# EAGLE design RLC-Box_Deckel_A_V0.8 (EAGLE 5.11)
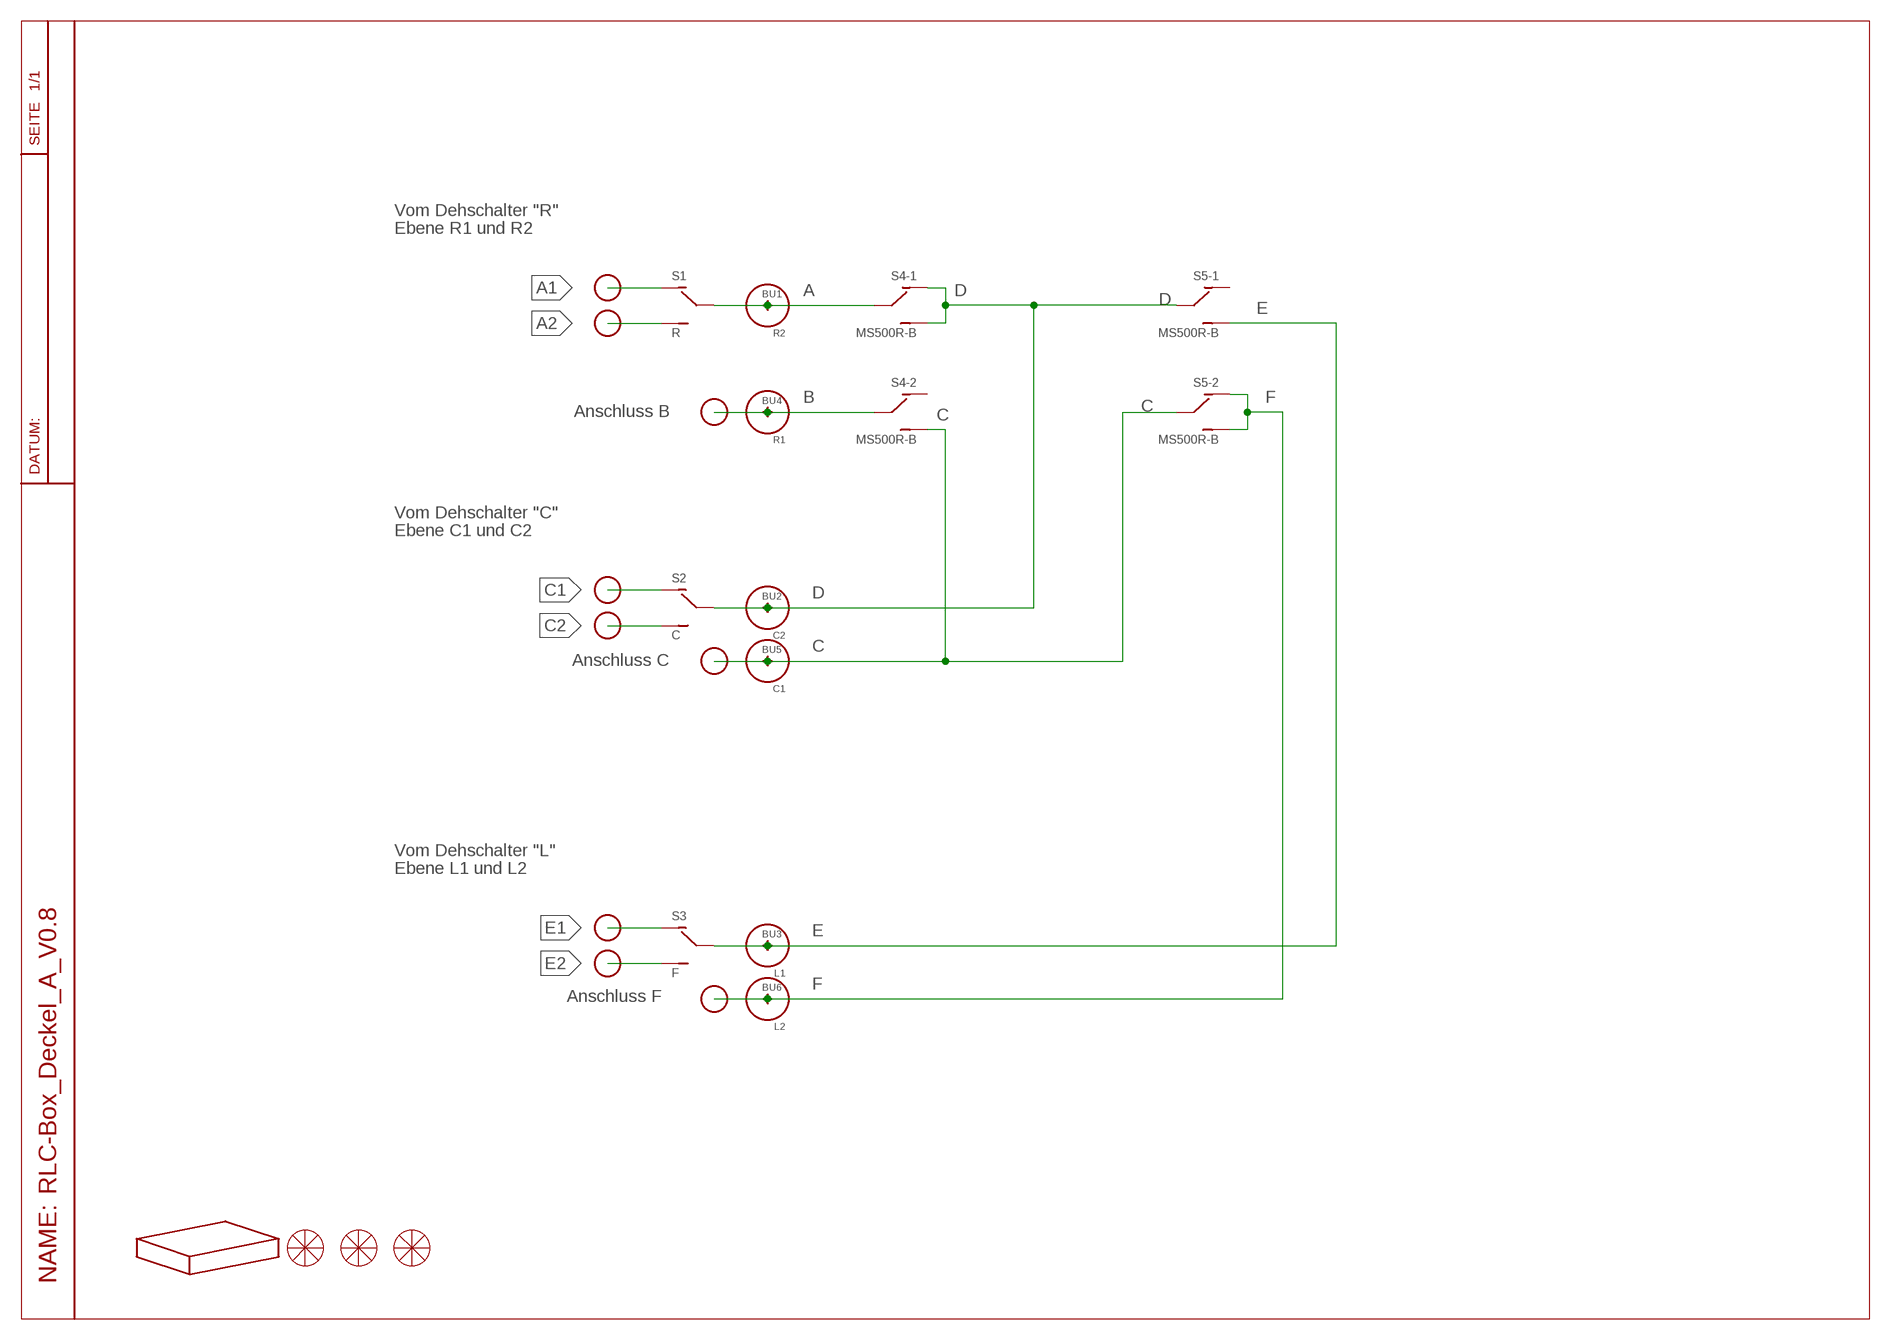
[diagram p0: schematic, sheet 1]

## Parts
BU1  R2  PK10AP  [PK10AP]
BU2  C2  PK10AP  [PK10AP]
BU3  L1  PK10AP  [PK10AP]
BU4  R1  PK10AP  [PK10AP]
BU5  C1  PK10AP  [PK10AP]
BU6  L2  PK10AP  [PK10AP]
P1  PAD-01  PAD-01SMD  [PAD-01-SMD]
P2  PAD-01  PAD-01SMD  [PAD-01-SMD]
P3  PAD-01  PAD-01SMD  [PAD-01-SMD]
P4  PAD-01  PAD-01SMD  [PAD-01-SMD]
P5  PAD-01  PAD-01SMD  [PAD-01-SMD]
P6  PAD-01  PAD-01SMD  [PAD-01-SMD]
P7  PAD-01  PAD-01SMD  [PAD-01-SMD]
P8  PAD-01  PAD-01SMD  [PAD-01-SMD]
P9  PAD-01  PAD-01SMD  [PAD-01-SMD]
S1  R  1XUMT1813  [T8013-1XUM]
S2  C  1XUMT1813  [T8013-1XUM]
S3  F  1XUMT1813  [T8013-1XUM]
S4  MS500R-B  MS500R-BT8011  [T8011-2XUM]
S5  MS500R-B  MS500R-BT8011  [T8011-2XUM]
U$1  DECKEL  [GEHÄUSE]
U$5  SKALA24  SKALA24K  [SKALE24]
U$6  SKALA24  SKALA24K  [SKALE24]
U$9  SKALA24  SKALA24G  [SKALE25-2]

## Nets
A: BU1.1 S1.2 S4.2
A1: P1.P$1 S1.1
A2: P2.P$1 S1.3
B: BU4.1 P3.P$1 S4.5
C: BU5.1 P6.P$1 S4.6 S5.5
C1: P4.P$1 S2.1
C2: P5.P$1 S2.3
D: BU2.1 S2.2 S4.1 S4.3 S5.2
E: BU3.1 S3.2 S5.3
E1: P7.P$1 S3.1
E2: P8.P$1 S3.3
F: BU6.1 P9.P$1 S5.4 S5.6
Unconnected: S4.4 S5.1

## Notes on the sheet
- Vom Dehschalter "R"
- Ebene R1 und R2
- Anschluss B
- Vom Dehschalter "C"
- Ebene C1 und C2
- Anschluss C
- Vom Dehschalter "L"
- Ebene L1 und L2
- Anschluss F

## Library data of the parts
BU1-BU6 = MB:PK10AP
P1-P9 = Connect:PAD-01
S1-S3 = Schalter:1XUM
S4 S5 = Schalter:MS500R-B
U$1 = RLC-BOX:DECKEL
U$5 U$6 U$9 = RLC-BOX:SKALA24

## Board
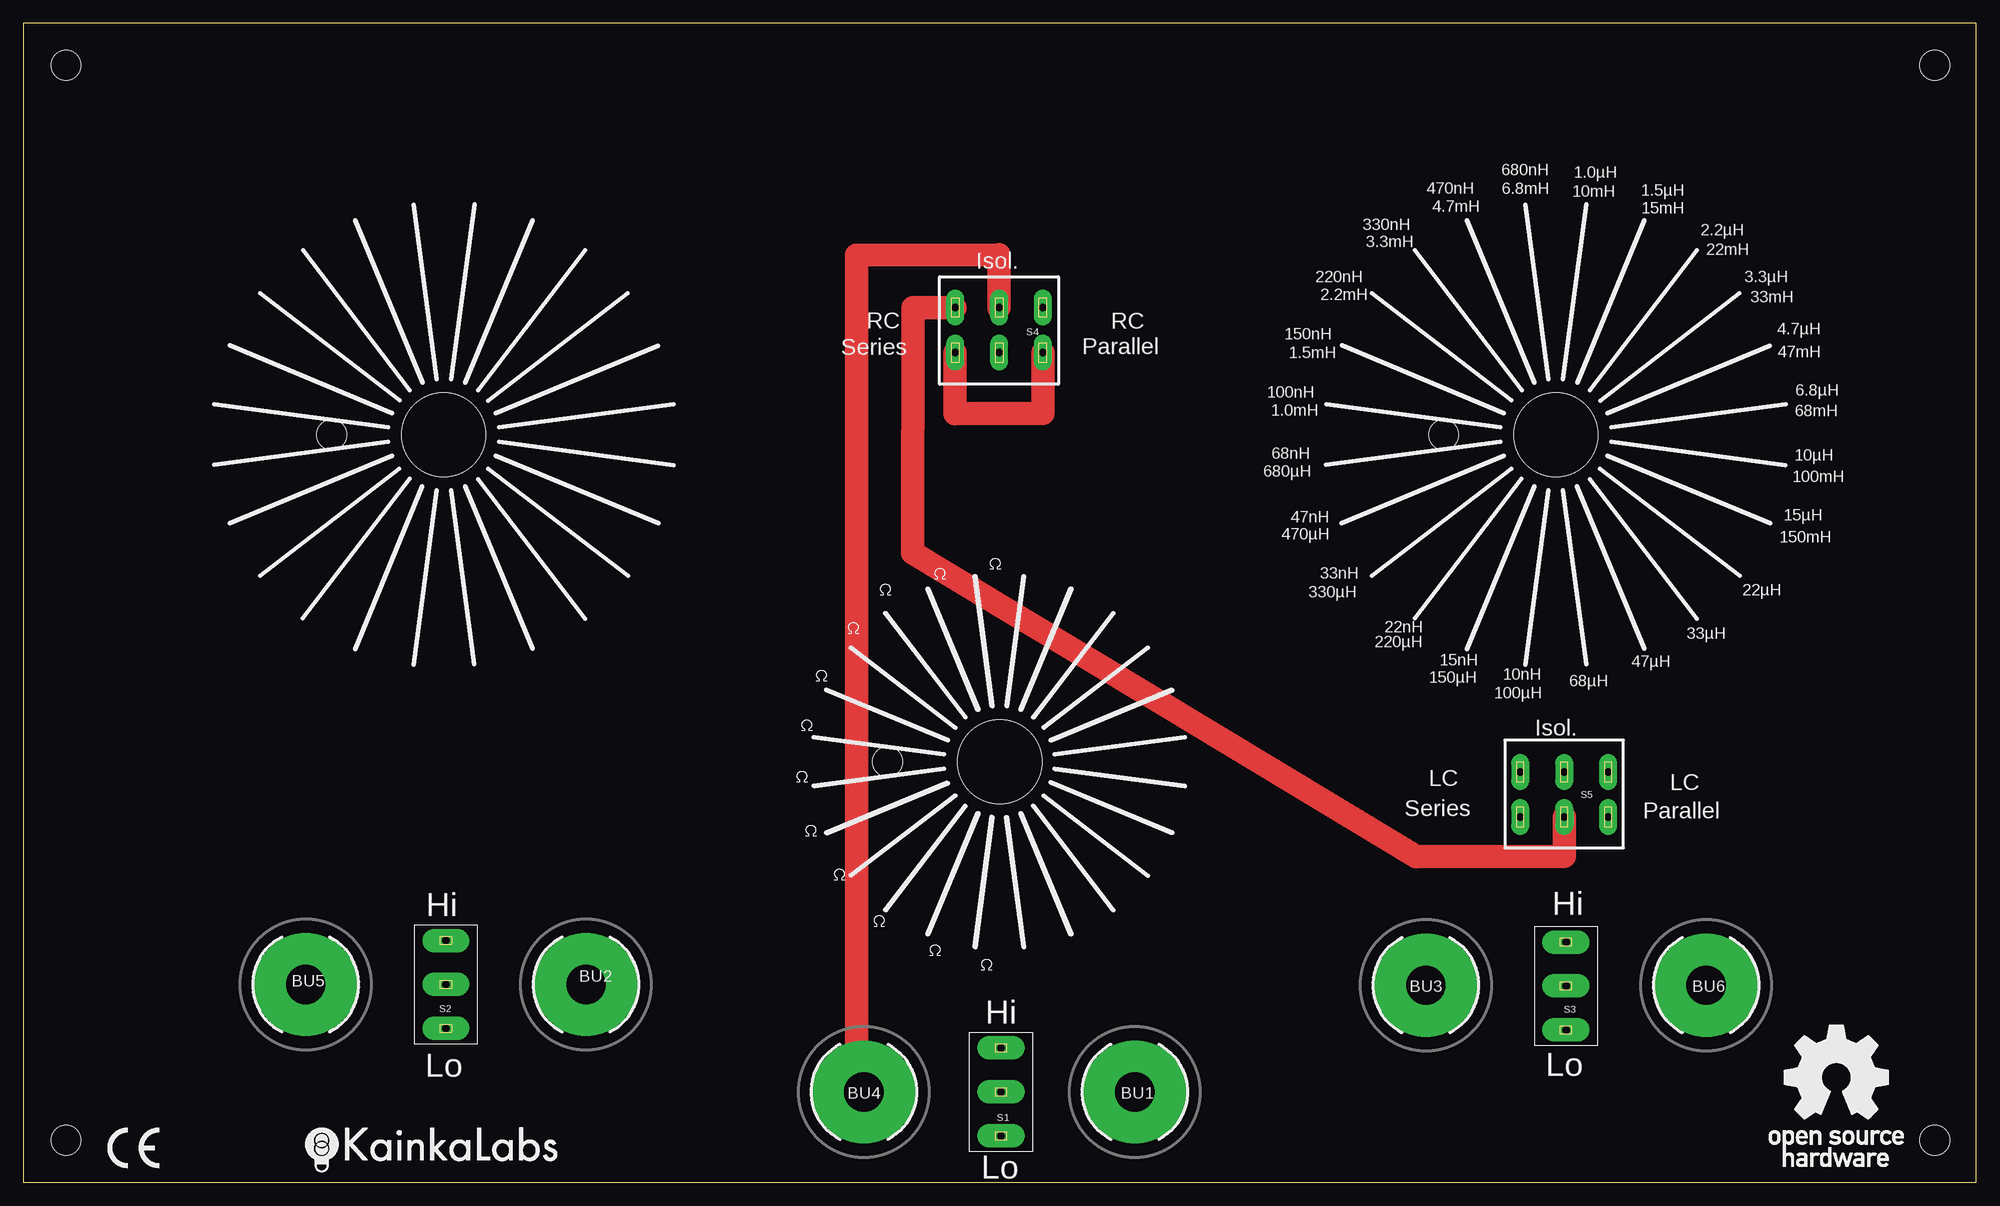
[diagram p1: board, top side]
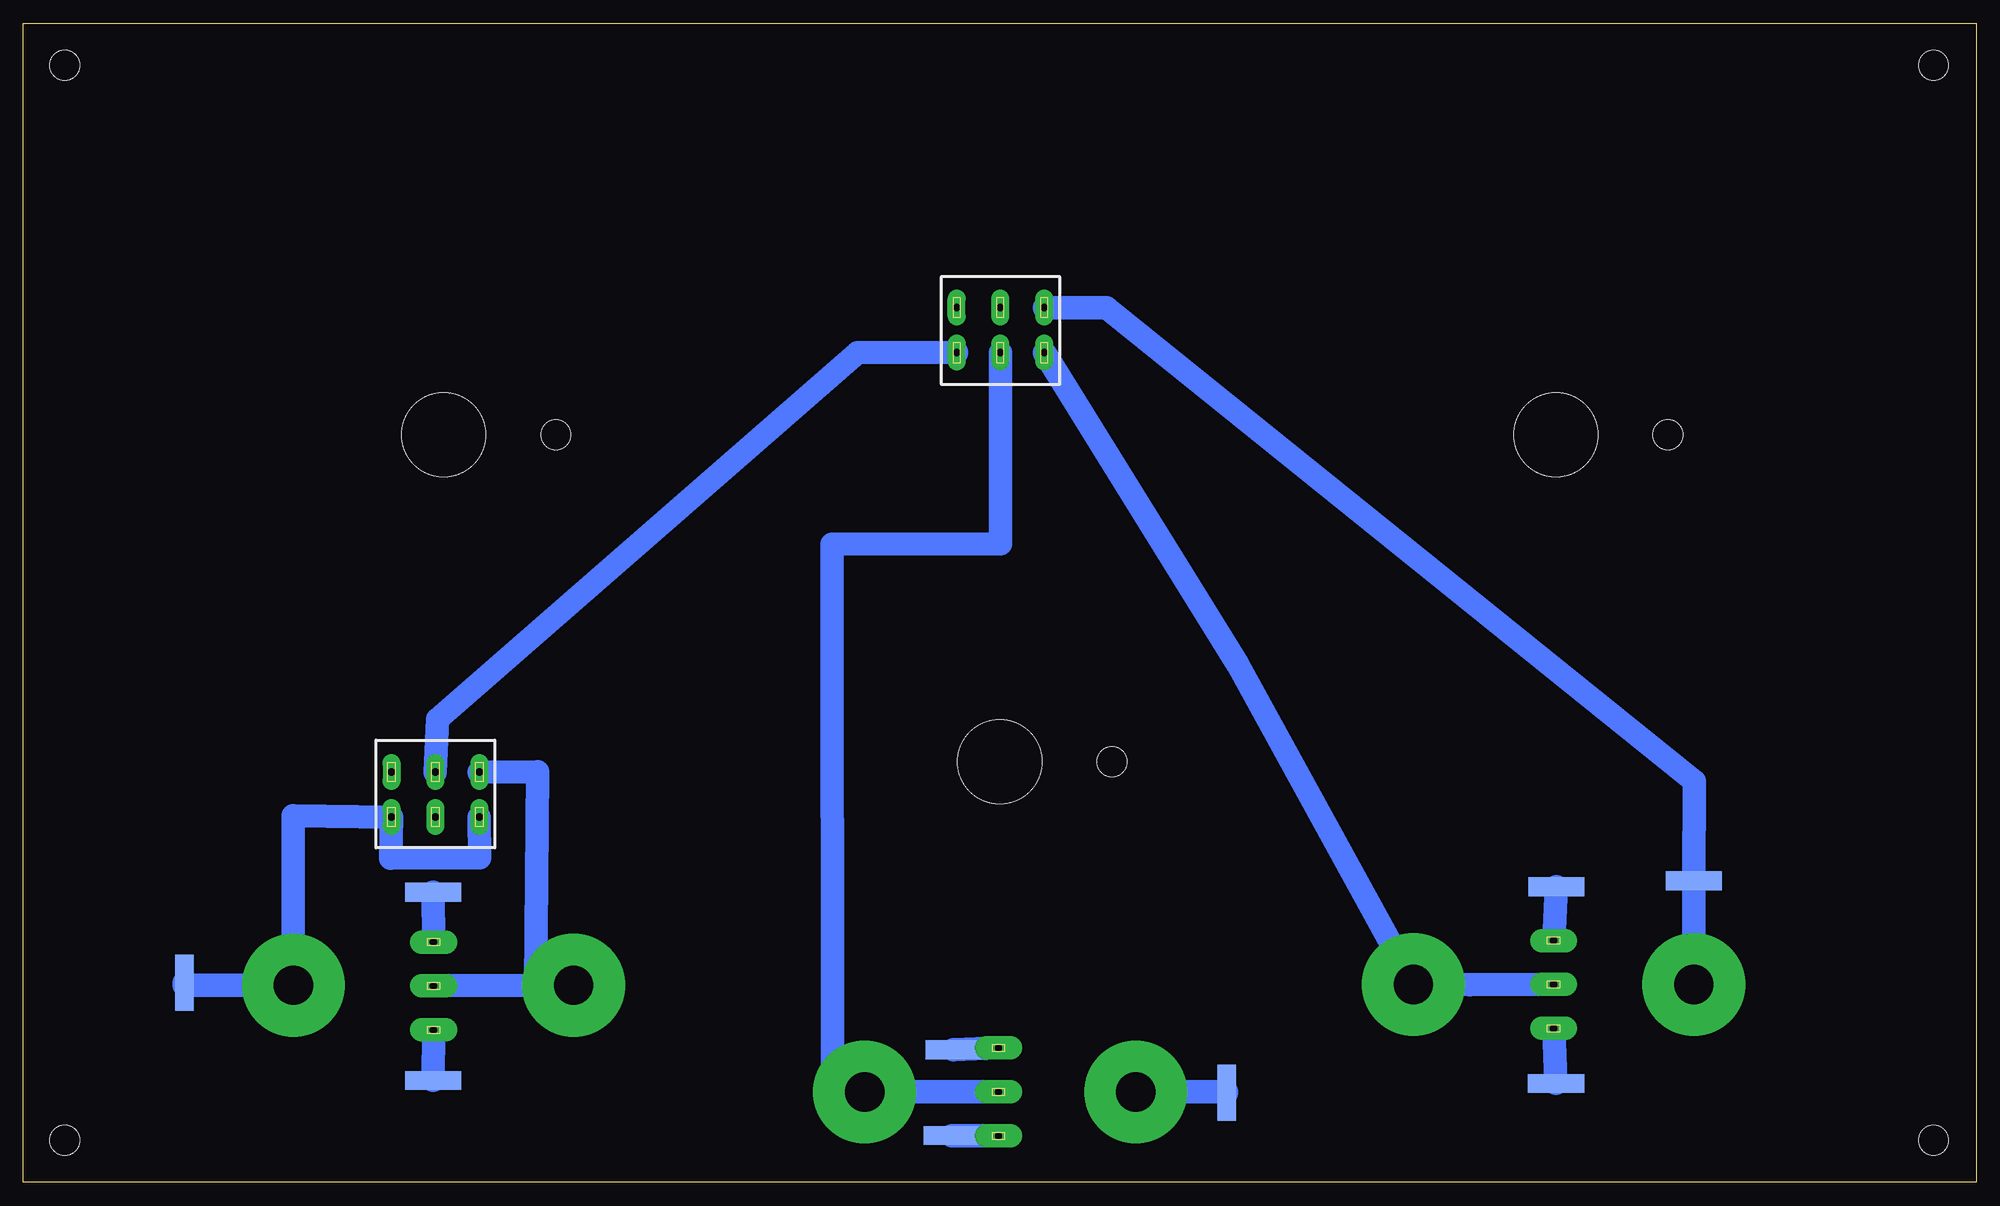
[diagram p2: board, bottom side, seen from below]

Size 209 x 124 mm. Coordinates in mm from the lower left corner, seen from the top.
Copper layers (1*16): Top 0.035mm / dielectric 1.5mm / Bottom 0.035mm
Design rules "default": minimum track width 10mil, minimum drill 23mil, track to track 8mil, track to pad 8mil, pad to pad 8mil, via to via 8mil, smd to smd 8mil, copper to edge 40mil, drill to drill 8mil, minimum pad ring 10mil, minimum via ring 8mil, stop-mask expansion 4mil, vias tented up to drill 0mil, thermal gap 20mil

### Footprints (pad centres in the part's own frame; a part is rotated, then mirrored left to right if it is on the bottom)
PK10AP = drill 4.2 pad 11 round: 1 0,0
PAD-01-SMD = smd 6 x 2: P$1 0,0
T8013-1XUM = drill 0.8 pad 2.54 long: 1 0,4.7; 2 0,0; 3 0,-4.7
T8011-2XUM = drill 0.8 pad 1.93 long: 1 -2.415,4.7; 2 -2.415,0; 3 -2.415,-4.7; 4 2.415,4.7; 5 2.415,0; 6 2.415,-4.7
GEHÄUSE = hole 3.2: 204.567,119.503; 204.567,4.503; 4.567,4.503; 4.567,119.503; 152,80; 92.5,45; 33,80 | hole 9: 164,80; 104.5,45; 45,80

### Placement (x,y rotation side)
BU1  118.96,9.67 0 top
BU2  60.22,21.16 0 top
BU3  150.11,21.09 0 top
BU4  89.96,9.67 0 top
BU5  30.22,21.16 0 top
BU6  180.11,21.09 0 top
P1  109.63,4.99 180 bottom
P2  109.46,14.19 0 bottom
P3  80.22,9.59 270 bottom
P4  44.96,10.57 0 bottom
P5  44.93,31.62 0 bottom
P6  30.23,32.26 180 bottom
P7  165.13,10.9 0 bottom
P8  165.13,31.04 0 bottom
P9  191.77,21.34 270 bottom
S1  104.63,9.67 180 top
S2  45.22,21.16 180 top
S3  165.1,21 180 top
S4  104.42,91.18 90 bottom
S5  164.9,41.48 270 top
U$1  0,0 0 top
U$2  [KAIKALABS27]  30.17,1.07 0 top
U$3  [CE6MM]  9.02,1.52 0 top
U$4  [OSH15MM]  186.82,1.65 0 top
U$5  104.41,45.02 0 top
U$6  104.5,45 0 top
U$7  SKALA24  [SKALE25-2]  164,80 0 top
U$9  45,80 0 top
U$11  [OHM1,5MM-S]  91.63,62.82 0 top
U$12  [OHM1,5MM-S]  97.46,64.5 0 top
U$13  [OHM1,5MM-S]  103.38,65.57 0 top
U$14  [OHM1,5MM-S]  88.2,58.7 0 top
U$15  [OHM1,5MM-S]  84.79,53.6 0 top
U$16  [OHM1,5MM-S]  83.21,48.28 0 top
U$17  [OHM1,5MM-S]  82.69,42.79 0 top
U$18  [OHM1,5MM-S]  83.65,37.03 0 top
U$19  [OHM1,5MM-S]  86.71,32.33 0 top
U$20  [OHM1,5MM-S]  90.96,27.36 0 top
U$21  [OHM1,5MM-S]  96.95,24.22 0 top
U$22  [OHM1,5MM-S]  102.45,22.69 0 top

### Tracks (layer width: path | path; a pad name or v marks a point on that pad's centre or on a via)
A
  Bottom 2.54: S1.2 BU1.1 122.41,9.67 122.45,68.28 104.39,68.33 S4.2
A1
  Bottom 2.54: S1.1 P1.P$1
A2
  Bottom 2.54: S1.3 P2.P$1
B
  Top 2.54: BU4.1 89.18,11.89 89.18,95.56 89.18,99.19 104.44,99.26 S4.5
  Bottom 2.54: BU4.1 80.22,9.67 P3.P$1
C
  Top 2.54: S4.6 95.2,93.57 95.15,67.36 149.1,34.82 164.95,34.9 S5.5
  Bottom 2.54: BU5.1 P6.P$1 30.15,42.93 93.09,93.57 S4.6
C1
  Bottom 2.54: P4.P$1 S2.1
C2
  Bottom 2.54: S2.3 P5.P$1
D
  Top 2.54: S4.3 99.69,82.22 109.14,82.27 109.12,82.27 S4.1
  Bottom 0.406: 59.94,21.26 BU2.1
  Bottom 2.54: S2.2 54.18,21.16 59.94,21.26 | BU2.1 78.99,55.35 S4.3 | S5.2 164.65,49.56 119.72,88.78 109.12,88.82 S4.1
E
  Bottom 2.54: BU3.1 S3.2 154.18,21.09 153.97,43.94 S5.3
E1
  Bottom 2.54: P7.P$1 S3.1
E2
  Bottom 2.54: S3.3 P8.P$1
F
  Bottom 2.54: S5.6 160.17,34.7 169.7,34.67 S5.4 180.14,39.19 BU6.1 191.77,21.09 P9.P$1

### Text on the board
tNames: 680nH | 1.0µH | 470nH | 6.8mH | 1.5µH | 10mH | 4.7mH | 15mH | 330nH | 2.2µH | 3.3mH | 22mH | Isol. | 220nH | 3.3µH | 2.2mH | 33mH | RC | RC | 4.7µH | 150nH | Series | Parallel | 1.5mH | 47mH | 100nH | 6.8µH | 1.0mH | 68mH | 68nH | 10µH | 680µH | 100mH | 47nH | 15µH | 470µH | 150mH | 33nH | 330µH | 22µH | 22nH | 33µH | 220µH | 15nH | 47µH | 10nH | 150µH | 68µH | 100µH | Isol. | LC | LC | Series | Parallel | Hi | Hi | Hi | Lo | Lo | Lo
tValues: C | L | RLC-Box | 680pF | 1.0nF | 470pF | 6.8µF | 10µF | 1.5nF | 4.7µF | 15µF | 2.2nF | 330pF | 3.3µF | 22µF | 3.3nF | 220pF | 33µF | 2.2µF | 150pF | 4.7nF | 1.5µF | 47µF | 100pF | 6.8nF | 1.0µF | 68µF | 68pF | 10nF | 680nF | 100µF | R | 15nF | 47pF | 150µF | 470nF | 82k | 100k | 68k | 120k | 680 | 1.0k | 1.2k | 33pF | 22nF | 470 | 330 | 150k | 330nF | 220µF | 56k | 1.5k | 33nF | 220 | 180k | 22pF | 330µF | 47k | 1.8k | 220nF | 15pF | 47nF | 150 | 220k | 150nF | 10pF | 68nF | 470µF | 39k | 2.2k | 100nF | 1000µF | 100 | 270k | 33k | 2.7k | 68 | 330k | 27k | 3.3k | 390k | 47 | 22k | 3.9k | 33 | 470k | 18k | 4.7k | 560k | 22 | 15k | 5.6k | 15 | 6.8k | 10 | 8.2k | 12k | 680k | 10k | 820k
